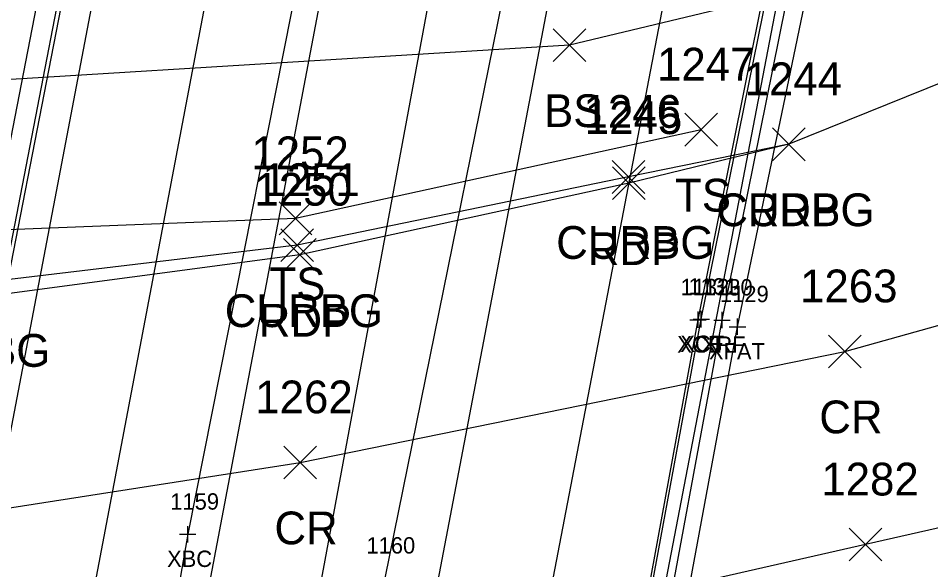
# Model space of a CAD drawing. Extents: x 1683147 to 1683637, y 416837 to 418211.
# Drawn here: x 1683224.4 to 1683280.1, y 417543.9 to 417577.5 of the extents above; entities that cross this region are included whole.
import ezdxf

# ---------------------------------------------------------------- set-up
doc = ezdxf.new("R2010")
doc.units = 0
for name, color, linetype in [('B_A', 7, 'Continuous'), ('B_I', 7, 'Continuous'), ('B_TIC', 7, 'Continuous'), ('BB', 7, 'Continuous'), ('BDC', 7, 'Continuous'), ('BELB', 7, 'Continuous'), ('BF', 7, 'Continuous'), ('BR', 7, 'Continuous'), ('L_A', 7, 'Continuous'), ('L_I', 7, 'Continuous'), ('L_TIC', 7, 'Continuous'), ('LELB', 7, 'Continuous'), ('P_A', 7, 'Continuous'), ('P_I', 7, 'Continuous'), ('P_TIC', 7, 'Continuous'), ('PET', 7, 'Continuous'), ('PRC', 7, 'Continuous'), ('R_A', 7, 'Continuous'), ('R_I', 7, 'Continuous'), ('R_TIC', 7, 'Continuous'), ('RC', 7, 'Continuous')]:
    doc.layers.add(name, color=color, linetype=linetype)

msp = doc.modelspace()

# ---------------------------------------------------------------- linework, layer by layer
at = {"layer": 'B_TIC'}
for p, q in [((1683265.94, 417559.114), (1683266.015, 417559.114)), ((1683266.141, 417559.151), (1683266.217, 417559.151)), ((1683267.409, 417559.099), (1683267.485, 417559.099)), ((1683268.351, 417558.692), (1683268.426, 417558.692)), ((1683234.784, 417546.02), (1683234.86, 417546.02))]:
    msp.add_line(p, q, dxfattribs=at)
for points in [[(1683265.936, 417558.614), (1683265.936, 417559.614)], [(1683266.138, 417558.651), (1683266.138, 417559.651)], [(1683267.406, 417558.599), (1683267.406, 417559.599)], [(1683265.436, 417559.114), (1683266.436, 417559.114)], [(1683265.638, 417559.151), (1683266.638, 417559.151)], [(1683266.906, 417559.099), (1683267.906, 417559.099)], [(1683268.347, 417558.192), (1683268.347, 417559.192)], [(1683267.847, 417558.692), (1683268.847, 417558.692)], [(1683234.781, 417545.52), (1683234.781, 417546.52)], [(1683234.281, 417546.02), (1683235.281, 417546.02)]]:
    msp.add_lwpolyline(points, dxfattribs=at)
at = {"layer": 'BB'}
for points in [[(1683247.534, 417457.283), (1683256.806, 417505.82), (1683275.504, 417603.185), (1683284.507, 417651.57)], [(1683240.224, 417455.825), (1683249.612, 417504.3), (1683268.309, 417601.755), (1683277.362, 417650.167)], [(1683233.056, 417454.423), (1683242.375, 417502.873), (1683260.963, 417600.277), (1683270.09, 417648.672)], [(1683225.817, 417452.979), (1683235.185, 417501.44), (1683252.981, 417597.315), (1683262.91, 417647.271)], [(1683218.639, 417451.571), (1683227.942, 417499.995), (1683246.282, 417596.559), (1683255.565, 417645.821)], [(1683211.398, 417450.232), (1683220.685, 417498.601), (1683239.091, 417595.537), (1683248.339, 417644.482)], [(1683204.248, 417448.864), (1683213.453, 417497.213), (1683232.034, 417594.621), (1683241.123, 417643.096)]]:
    msp.add_lwpolyline(points, dxfattribs=at)
at = {"layer": 'BDC'}
for points in [[(1683248.051, 417455.436), (1683253.896, 417491.851), (1683257.783, 417514.592), (1683265.936, 417559.114), (1683272.886, 417593.685), (1683281.07, 417631.095), (1683286.315, 417653.984)], [(1683248.206, 417455.394), (1683254.065, 417491.776), (1683257.952, 417514.755), (1683266.138, 417559.151), (1683273.116, 417593.593), (1683281.173, 417630.923), (1683286.527, 417654.075)], [(1683204.26, 417446.59), (1683207.746, 417469.989), (1683213.462, 417505.801), (1683221.311, 417549.93), (1683228.046, 417584.722), (1683234.074, 417613.621), (1683241.065, 417645.18)], [(1683204.523, 417446.635), (1683207.943, 417470.136), (1683213.692, 417505.86), (1683221.542, 417549.946), (1683228.342, 417584.807), (1683234.248, 417613.515), (1683241.392, 417644.923)]]:
    msp.add_lwpolyline(points, dxfattribs=at)
at = {"layer": 'BELB'}
for points in [[(1683269.206, 417650.948), (1683260.393, 417611.397), (1683256.447, 417590.785), (1683246.822, 417543.339), (1683241.399, 417511.39), (1683234.932, 417474.067), (1683231.661, 417452.147)], [(1683255.821, 417648.166), (1683248.035, 417613.702), (1683243.06, 417587.805), (1683234.781, 417546.02), (1683228.274, 417508.761), (1683222.317, 417473.758), (1683218.863, 417449.537)]]:
    msp.add_lwpolyline(points, dxfattribs=at)
at = {"layer": 'BF'}
msp.add_lwpolyline([(1683250.624, 417454.9), (1683256.47, 417491.459), (1683260.265, 417514.98), (1683268.347, 417558.692), (1683275.679, 417593.916), (1683283.544, 417630.285), (1683288.924, 417653.565)], dxfattribs=at)
at = {"layer": 'BR'}
for points in [[(1683248.519, 417448.641), (1683249.479, 417455.186), (1683255.278, 417491.444), (1683259.237, 417514.807), (1683267.406, 417559.099), (1683274.406, 417593.753), (1683282.508, 417630.53), (1683290.526, 417665.488)], [(1683201.249, 417434.944), (1683203.019, 417446.95), (1683206.413, 417469.882), (1683212.207, 417505.421), (1683220.042, 417550.002), (1683226.73, 417584.319), (1683232.917, 417613.974), (1683239.772, 417645.191), (1683242.155, 417655.448)]]:
    msp.add_lwpolyline(points, dxfattribs=at)
at = {"layer": 'L_TIC'}
for points in [[(1683257.094, 417574.88), (1683259.094, 417576.88)], [(1683259.094, 417574.88), (1683257.094, 417576.88)], [(1683265.126, 417569.722), (1683267.126, 417571.722)], [(1683267.126, 417569.722), (1683265.126, 417571.722)], [(1683240.357, 417564.306), (1683242.357, 417566.306)], [(1683242.357, 417564.306), (1683240.357, 417566.306)]]:
    msp.add_lwpolyline(points, dxfattribs=at)
at = {"layer": 'LELB'}
for points in [[(1683286.499, 417582.7), (1683258.094, 417575.88), (1683207.744, 417572.779)], [(1683266.126, 417570.722), (1683241.357, 417565.306), (1683221.182, 417564.496), (1683207.672, 417565.784)]]:
    msp.add_lwpolyline(points, dxfattribs=at)
at = {"layer": 'P_TIC'}
for points in [[(1683270.475, 417568.828), (1683272.475, 417570.828)], [(1683272.475, 417568.828), (1683270.475, 417570.828)], [(1683260.715, 417566.454), (1683262.715, 417568.454)], [(1683262.715, 417566.454), (1683260.715, 417568.454)], [(1683240.63, 417562.083), (1683242.63, 417564.083)], [(1683242.63, 417562.083), (1683240.63, 417564.083)], [(1683273.909, 417556.18), (1683275.909, 417558.18)], [(1683275.909, 417556.18), (1683273.909, 417558.18)], [(1683240.64, 417549.402), (1683242.64, 417551.402)], [(1683242.64, 417549.402), (1683240.64, 417551.402)], [(1683275.156, 417544.385), (1683277.156, 417546.385)], [(1683277.156, 417544.385), (1683275.156, 417546.385)]]:
    msp.add_lwpolyline(points, dxfattribs=at)
at = {"layer": 'PET'}
msp.add_lwpolyline([(1683444.524, 417639.397), (1683404.458, 417622.242), (1683363.803, 417604.981), (1683316.848, 417587.705), (1683293.07, 417578.551), (1683271.475, 417569.828), (1683261.715, 417567.454), (1683241.63, 417563.083), (1683221.134, 417560.361), (1683207.789, 417560.65)], dxfattribs=at)
at = {"layer": 'PRC'}
for points in [[(1683206.154, 417544.862), (1683241.64, 417550.402), (1683274.909, 417557.18), (1683311.228, 417567.333), (1683337.826, 417576.227), (1683364.361, 417586.18)], [(1683342.592, 417562.589), (1683311.955, 417553.502), (1683276.156, 417545.385), (1683245.179, 417538.35), (1683203.393, 417531.667)]]:
    msp.add_lwpolyline(points, dxfattribs=at)
at = {"layer": 'R_TIC'}
for points in [[(1683270.475, 417568.828), (1683272.475, 417570.828)], [(1683272.475, 417568.828), (1683270.475, 417570.828)], [(1683260.694, 417566.834), (1683262.694, 417568.834)], [(1683262.694, 417566.834), (1683260.694, 417568.834)], [(1683240.458, 417562.668), (1683242.458, 417564.668)], [(1683242.458, 417562.668), (1683240.458, 417564.668)]]:
    msp.add_lwpolyline(points, dxfattribs=at)
at = {"layer": 'RC'}
msp.add_lwpolyline([(1683271.475, 417569.828), (1683261.694, 417567.834), (1683241.458, 417563.668), (1683221.147, 417561.243), (1683207.845, 417561.271)], dxfattribs=at)

# ---------------------------------------------------------------- texts
at = {"layer": 'B_A'}
for s, p in [('XCB', (1683264.672, 417557.114)), ('XCT', (1683264.858, 417557.151)), ('XRF', (1683266.165, 417557.099)), ('XFAT', (1683266.603, 417556.692)), ('XBC', (1683233.517, 417544.02))]:
    msp.add_text(s, height=1, dxfattribs=at).set_placement(p)
at = {"layer": 'B_I'}
for s, p in [('1132', (1683264.873, 417560.614)), ('1131', (1683265.358, 417560.651)), ('1130', (1683266.299, 417560.599)), ('1129', (1683267.28, 417560.192)), ('1159', (1683233.714, 417547.52)), ('1160', (1683245.692, 417544.839))]:
    msp.add_text(s, height=1, dxfattribs=at).set_placement(p)
at = {"layer": 'L_A'}
for s, p in [('BS', (1683256.535, 417570.88)), ('TS', (1683264.535, 417565.722)), ('TS', (1683239.767, 417560.306))]:
    msp.add_text(s, height=2, dxfattribs=at).set_placement(p)
at = {"layer": 'L_I'}
for s, p in [('1247', (1683263.433, 417573.722)), ('1252', (1683238.665, 417568.306))]:
    msp.add_text(s, height=2, dxfattribs=at).set_placement(p)
at = {"layer": 'P_A'}
for s, p in [('RDP', (1683268.963, 417564.828)), ('RDP', (1683259.203, 417562.454)), ('RDP', (1683239.118, 417558.083)), ('CR', (1683273.342, 417552.18)), ('CR', (1683240.073, 417545.402))]:
    msp.add_text(s, height=2, dxfattribs=at).set_placement(p)
at = {"layer": 'P_I'}
for s, p in [('1244', (1683268.782, 417572.828)), ('1245', (1683259.023, 417570.454)), ('1250', (1683238.85, 417566.083)), ('1263', (1683272.169, 417560.18)), ('1262', (1683238.9, 417553.402)), ('1282', (1683273.464, 417548.385))]:
    msp.add_text(s, height=2, dxfattribs=at).set_placement(p)
at = {"layer": 'R_A'}
for p in [(1683267.057, 417564.828), (1683257.277, 417562.834), (1683237.04, 417558.668), (1683216.73, 417556.243)]:
    msp.add_text('CURBG', height=2, dxfattribs=at).set_placement(p)
at = {"layer": 'R_I'}
for s, p in [('1244', (1683268.782, 417572.828)), ('1246', (1683258.946, 417570.834)), ('1251', (1683239.332, 417566.668))]:
    msp.add_text(s, height=2, dxfattribs=at).set_placement(p)

doc.saveas('drawing.dxf')
